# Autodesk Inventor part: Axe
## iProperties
Shininess: 64.0
Length Units: 11269
Angle Units: 11279
Time Units: 11290
Mass Units: 11283
Length Display Precision: 3
Angle Display Precision: 2
Compacted: True
Part Number: Axe
Document SubType Name: Modeling
Created: 2003-05
Material: Par défaut
Designer: Philippe
Density: 0.0
Volumn: 0.0
Area: 0.0
PropertySet Name: Model Information
Control State: 0
Master: False
Checked Out: False
Author: Philippe
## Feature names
1. Révolution1 [Revolution]
2. Extrusion1
3. Chanfrein1 [Chamfer]
